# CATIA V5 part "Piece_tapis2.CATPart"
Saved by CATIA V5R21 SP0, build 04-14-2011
Part number: Piece tapis2
Bounding box of the stored display mesh (mm): x -16.498 to 16.498, y -16.498 to 16.498, z 0 to 10.393
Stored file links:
  C:\Users\Raphael\Documents\Imprimante 3D\Tapis voiture Hyundai Elantra 2014\Piece tapis2.CATPart
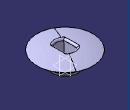
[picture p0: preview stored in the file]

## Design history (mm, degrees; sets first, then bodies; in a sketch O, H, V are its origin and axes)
Body1 (main body)
  Sketch1 on yz-plane, origin (0, 0, 0), H (0, 1, 0), V (0, 0, 1)
    axis line L1 (0, 57.5114) -> (0, -52.3513)
    point P1 (0, 57.5114)
    point P3 (0, 0)
    line L2 (0, 0) -> (-8.9, 0)
    line L3 (-8.9, 0) -> (-8.9, 3)
    line L4 (-8.9, 3) -> (-7.5, 3)
    line L5 (-7.5, 3) -> (-7.5, 8)
    line L6 (-7.5, 8) -> (-16.5, 8)
    point P8 (-16.5, 8)
    line L7 (0, 0) -> (0, 10.5)
    point P9 (0, 10.5)
    arc A1 centre (-0.8648, -39.4925) radius 50 from (-16.5, 8) to (0, 10.5) cw
    "Radius" L1 L3 = 8.9
    distance L2 L4 = 3
    "Radius" L5 L1 = 7.5
    distance P9 L2 = 10.5
    distance L6 L2 = 8
    "Radius" P8 L1 = 16.5
    radius A1 = 50
    coincidence: P1 V, P3 H, P3 L1, O P3
    vertical: L1 V, L3 V, L5 V, L7 V
    horizontal: L2 H, L4 H, L6 H
  Shaft1: profile Sketch1, axis Sketch1.L1, angle 360
  Chamfer1: length 2, angle 30, on edge [face of Shaft1 from Sketch1.L3 | face of Shaft1 from Sketch1.L2]
  Sketch2 on xy-plane, origin (0, 0, 0), H (1, 0, 0), V (0, 1, 0)
    line L1 (-4, 4.2525) -> (-4, -4.2525)
    line L2 (4, -4.2525) -> (4, 4.2525)
    point P2 (-4, 4.2525)
    point P3 (-4, -4.2525)
    offset circle E2 centre (0, 0) radius 5.8382 from edge [face of Chamfer1 | face of Shaft1 from Sketch1.L2]
    offset arc E3 centre (0, 0) radius 5.8382 from (4, 4.2525) to (-4, 4.2525) ccw from edge [face of Chamfer1 | face of Shaft1 from Sketch1.L2]
    offset arc E4 centre (0, 0) radius 5.8382 from (-4, -4.2525) to (4, -4.2525) ccw from edge [face of Chamfer1 | face of Shaft1 from Sketch1.L2]
    distance L1 L2 = 8
    distance V L1 = 4
    vertical: L1 V, L2 V
    coincidence: E2 P2, P3 E2
  Pocket1: profile Sketch2, direction (0, 0, 1), through (limit type 3)
  Draft1: Angle 5, Neutral face of Shaft1 from Sketch1.L2, PullDir face of Shaft1 from Sketch1.L2, SupportToDraft (face of Pocket1 from Sketch2.E4; face of Pocket1 from Sketch2.L1; face of Pocket1 from Sketch2.L2; face of Pocket1 from Sketch2.E4)
  Fillet1: radius 1, on edge [face of Pocket1 from Sketch2.E4 | face of Shaft1 from Sketch1.L2] (x2); edge [face of Pocket1 from Sketch2.L1 | face of Shaft1 from Sketch1.L2]; edge [face of Pocket1 from Sketch2.L2 | face of Shaft1 from Sketch1.L2]
  Fillet2: radius 1, on edge [face of Pocket1 from Sketch2.E4 | face of Shaft1 from Sketch1.A1] (x2); edge [face of Pocket1 from Sketch2.L2 | face of Shaft1 from Sketch1.A1]; edge [face of Pocket1 from Sketch2.L1 | face of Shaft1 from Sketch1.A1]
